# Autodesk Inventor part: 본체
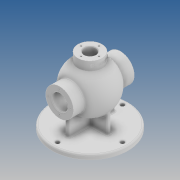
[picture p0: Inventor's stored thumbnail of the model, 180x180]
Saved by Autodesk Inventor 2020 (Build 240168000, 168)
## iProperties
Created: 2020-08
Part Number: 본체
Material: 일반
Document SubType Name: Modeling
Designer: EZDESIGN
Density: 1 g/cm^3
Appearance: 기본값
Author: EZDESIGN
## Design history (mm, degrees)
sketch "스케치1"
  geometry: C1 r 85 at (0, 0); 1 further point
  constraints: 1 centre point, 1 coincident
  dimensions: "d0" = 170 diameter of C1
extrude "돌출1" new body sketch "스케치1" distance "d1" = 10; taper "d2" = 0 deg
sketch "스케치2"
  geometry: L1 (85, 68)-(85, -68); L2 (0, -85)-(0, 85) reference; A1 r 53 centre (85, 0) between (85, -53) and (85, 53); 2 further points
  constraints: 2 end point, 2 point on circle, 2 point on line, 1 centre point, 1 coincident, 1 horizontal alignment, 1 midpoint, 1 vertical
  dimensions: "d3" = 136 distance of L1.start L1.end; "d4" = 85 distance between parallel lines of L2 L1; "d5" = 106 diameter of A1
revolve "회전1" sketch "스케치2" stored, may be unused: angle "d6" = 90 deg
sketch "스케치3"
  geometry: L1 (85, 68)-(85, -68); L2 (85, 68)-(116, 68); L3 (116, 68)-(116, 42.988); 4 further points
  constraints: 6 end point, 1 coincident, 1 horizontal, 1 midpoint, 1 perpendicular, 1 vertical, 1 vertical alignment, 2 other
  dimensions: "d7" = 136 distance of L1.start L1.end; "d8" = 62 diameter of L3 L1
revolve "회전2" sketch "스케치3" stored, may be unused: angle "d9" = 90 deg
node "작업 평면2"
sketch "스케치4"
  geometry: C1 r 27 at (0, 0); 1 further point
  constraints: 1 centre point, 1 coincident
  dimensions: "d11" = 54 diameter of C1
extrude "돌출2" join sketch "스케치4" distance "d12" = 50; taper "d13" = 0 deg
sketch "스케치5"
  geometry: L1 (54, 68)-(54, 42.988) reference; L2 (54, -42.988)-(54, -68) reference; L3 (10, -85)-(10, 85) reference; L4 (54, 52)-(10, 52); L5 (67.304, -52)-(10, -52); L6 (54, 52)-(67.304, 52); L7 (67.304, 52)-(67.304, -52); A1 r 53 centre (85, 0) between (54, 42.988) and (116, 42.988) reference; 3 further points
  constraints: 8 end point, 3 perpendicular, 3 point on line, 1 horizontal
  dimensions: "d14" = 104 distance between parallel lines of L4 L5; "d15" = 52 distance from line of point (0, 0) L5; "d16" = 13.30408 distance of L4.start L6.end
extrude "돌출3" join sketch "스케치5" stored distance "d17" = 8; taper "d18" = 0 deg
sketch "스케치6"
  geometry: L1 (85, 10)-(-85, 10) reference; L2 (43, 54.016)-(43, 10); A1 r 53 centre (0, 85) between (-27, 130.607) and (27, 130.607) reference; 1 further point
  constraints: 2 end point, 1 perpendicular, 1 point on circle, 1 point on line
  dimensions: "d20" = 43 distance from line of point (0, 0) L2
feature "리브1" sketch "스케치6" dims "d21" = 1, "d22" = 8, "d23" = 0, "d24" = 0, "d25" = 1, "d26" = 1
sketch "스케치7"
  geometry: L1 (85, -43)-(85, 43); A1 r 53 centre (85, 0) between (116, -42.988) and (116, 42.988) reference; A2 r 43 centre (85, 0) between (85, -43) and (85, 43); 2 further points
  constraints: 2 coincident, 2 end point, 2 point on circle, 1 centre point, 1 midpoint, 1 vertical, 1 vertical alignment
  dimensions: "d27" = 86 distance of L1.start L1.end
revolve "회전3" sketch "스케치7" stored, may be unused: angle "d28" = 90 deg
sketch "스케치8"
  geometry: L1 (54, -68)-(116, -68) reference; L2 (54, 68)-(116, 68) reference; L3 (85, -68)-(85, 68); L4 (102.5, -68)-(102.5, -52); L5 (102.5, -52)-(103.5, -52); L6 (103.5, -52)-(103.5, -50.25); L7 (103.5, -50.25)-(102.5, -50.25); L8 (102.5, -50.25)-(102.5, 68); 1 further point
  constraints: 12 end point, 4 point on line, 3 perpendicular, 2 midpoint, 1 vertical
  dimensions: "d29" = 16 distance of L4.start L4.end; "d30" = 35 diameter of L4 L3; "d31" = 37 diameter of L6 L3; "d32" = 1.75 distance of L5.end L6.end
revolve "회전4" sketch "스케치8" stored, may be unused: angle "d33" = 90 deg
sketch "스케치9"
  geometry: C1 r 13 at (0, 0); 1 further point
  constraints: 1 centre point, 1 coincident
  dimensions: "d34" = 26 diameter of C1
extrude "돌출4" cut sketch "스케치9" distance "d35" = 40; taper "d36" = 0 deg
sketch "스케치10"
  geometry: C1 r 17.5 at (0, 0) reference; 5 further points
  constraints: 1 vertical alignment, 5 other
  dimensions: "d37" = 24 distance of C1.centre point (0, 24); "d40" = 360 deg dimension on C1.centre point (0, 24) (derived)
hole "구멍1" sketch "스케치10" at (0, 24), (-24, 0), (0, -24), (24, 0) diameter "d42" = 3.242; stored, may be unused: countersink angle "d46" = 90 deg, drill point angle "d48" = 118 deg; dims "d43" = 12, "d44" = 4, "d45" = 2, "d47" = 15
sketch "스케치11"
  geometry: C1 r 17.5 at (0, 0) reference; 5 further points
  constraints: 1 vertical alignment, 5 other
  dimensions: "d49" = 24 distance of C1.centre point (0, 24); "d52" = 360 deg dimension on C1.centre point (0, 24) (derived)
hole "구멍2" sketch "스케치11" at (0, 24), (-24, 0), (0, -24), (24, 0) diameter "d54" = 3.242; stored, may be unused: countersink angle "d58" = 90 deg, drill point angle "d60" = 118 deg; dims "d55" = 12, "d56" = 4, "d57" = 2, "d59" = 15
sketch "스케치12"
  geometry: C1 r 4.5 at (0, 72.5); C2 r 4.5 at (-72.5, 0); C3 r 4.5 at (0, -72.5); C4 r 4.5 at (72.5, 0); 1 further point
  constraints: 4 centre point, 1 vertical alignment, 9 other
  dimensions: "d61" = 9 diameter of C1; "d62" = 72.5 distance of point (0, 0) C1.centre; "d65" = 360 deg dimension on point (0, 0) C1.centre (derived)
extrude "돌출5" cut sketch "스케치12" distance "d67" = 40; taper "d68" = 0 deg
fillet "모깎기1" dims "d69" = 3
fillet "모깎기2" dims "d70" = 3
fillet "모깎기3" dims "d71" = 3
fillet "모깎기4" dims "d72" = 3
fillet "모깎기5" dims "d73" = 3
chamfer "모따기1" distance "d74" = 1; stored, may be unused: second distance "d75" = 2, angle "d76" = 45 deg
chamfer "모따기2" distance "d77" = 1; stored, may be unused: second distance "d78" = 2, angle "d79" = 45 deg
chamfer "모따기3" distance "d80" = 1; stored, may be unused: second distance "d81" = 2, angle "d82" = 45 deg
sketch "스케치13"
  geometry: 5 further points
  constraints: 1 horizontal alignment, 5 other
  dimensions: "d83" = 20 distance of point (0, 0) point (20, 0); "d86" = 360 deg dimension on point (0, 0) point (20, 0) (derived)
hole "구멍3" sketch "스케치13" at (20, 0), (0, 20), (-20, 0), (0, -20) diameter "d88" = 3.242; stored, may be unused: countersink angle "d92" = 90 deg, drill point angle "d94" = 118 deg; dims "d89" = 12, "d90" = 4, "d91" = 2, "d93" = 15
node "작업 평면3"
sketch "스케치14"
  geometry: L1 (150, -27)-(150, 27) reference; 2 further points
  constraints: 1 horizontal alignment, 1 other
  dimensions: "d96" = 9 distance from line of L1 point (141, 0)
feature "엠보싱1" sketch "스케치14" dims "d1" = 10, "d97" = 0.5, "d98" = 0
node "솔리드1"
mirror "미러1"
mirror "미러2"
node "작업 평면1"
feature "A9D066F2-1C7D-4E18-AEED-F7BC21143FA4" dims "d54" = 3.242, "d55" = 12, "d56" = 4, "d57" = 2, "d58" = 90 deg, "d59" = 15, "d60" = 118 deg
other parameters: "d95" = 110.5
